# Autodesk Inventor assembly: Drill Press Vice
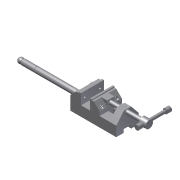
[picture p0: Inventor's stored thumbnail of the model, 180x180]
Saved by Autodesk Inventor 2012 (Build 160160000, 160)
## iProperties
Created: 2009-05
Part Number: Drill Press Vice
Document SubType Name: Assembly
Designer: Sham
Author: Sham
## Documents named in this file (9)
- C:\Users\CadCim\Documents\SAILESH\inventor-2011-fact-prt\c13-inv-2011-prt\c13_inv_2012_prt\fig-13-5 to 13-8\Drill Press Vice.iam
- C:\Users\CadCim\Documents\SAILESH\inventor-2011-fact-prt\c13-inv-2011-prt\c13_inv_2012_prt\fig-13-5 to 13-8\Base.ipt
- C:\Users\CadCim\Documents\SAILESH\inventor-2011-fact-prt\c13-inv-2011-prt\c13_inv_2012_prt\fig-13-5 to 13-8\Safety Handle.ipt
- C:\Users\CadCim\Documents\SAILESH\inventor-2011-fact-prt\c13-inv-2011-prt\c13_inv_2012_prt\fig-13-5 to 13-8\Jaw Face.ipt
- C:\Users\CadCim\Documents\SAILESH\inventor-2011-fact-prt\c13-inv-2011-prt\c13_inv_2012_prt\fig-13-5 to 13-8\Movable Jaw.ipt
- C:\Users\CadCim\Documents\SAILESH\inventor-2011-fact-prt\c13-inv-2011-prt\c13_inv_2012_prt\fig-13-5 to 13-8\Cap Screw.ipt
- C:\Users\CadCim\Documents\SAILESH\inventor-2011-fact-prt\c13-inv-2011-prt\c13_inv_2012_prt\fig-13-5 to 13-8\Clamp Screw Handle.ipt
- C:\Users\CadCim\Documents\SAILESH\inventor-2011-fact-prt\c13-inv-2011-prt\c13_inv_2012_prt\fig-13-5 to 13-8\Clamp Screw.ipt
- C:\Users\CadCim\Documents\SAILESH\inventor-2011-fact-prt\c13-inv-2011-prt\c13_inv_2012_prt\fig-13-5 to 13-8\Handle Stop.ipt
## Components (13 placed, 8 different names)
1. Base:1 — Mate:2, Mate:3, Mate:7, Insert:10, Insert:11, Insert:12, Insert:13
2. Safety Handle:1
3. Jaw Face:1 — Insert:8, Insert:9, Mate:7
4. Jaw Face:2 — Insert:10, Insert:11
5. Movable Jaw:1 — Mate:2, Mate:3, Insert:2, Insert:3, Insert:4, Insert:8, Insert:9
6. Cap Screw:1 — Insert:2
7. Cap Screw:2 — Insert:3
8. Cap Screw:3 — Insert:13
9. Cap Screw:4 — Insert:12
10. Clamp Screw:1 — Insert:4, Mate:6, Rotation/Translation:2
11. Clamp Screw Handle:1 — Mate:6, Insert:5, Insert:6, Rotation/Translation:2
12. Handle Stop:1 — Insert:6, Mate:8
13. Handle Stop:2 — Insert:5
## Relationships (17: Insert 11, Mate 5, RelateRotateTranslate 1)
- Mate:2: Base:1 ↔ Movable Jaw:1
- Mate:3: Base:1 ↔ Movable Jaw:1
- Insert:2: Movable Jaw:1 ↔ Cap Screw:1
- Insert:3: Movable Jaw:1 ↔ Cap Screw:2
- Insert:4: Movable Jaw:1 ↔ Clamp Screw:1
- Mate:6: Clamp Screw:1 ↔ Clamp Screw Handle:1
- Insert:5: Clamp Screw Handle:1 ↔ Handle Stop:2
- Insert:6: Clamp Screw Handle:1 ↔ Handle Stop:1
- Insert:8: Jaw Face:1 ↔ Movable Jaw:1
- Insert:9: Jaw Face:1 ↔ Movable Jaw:1
- Mate:7: Base:1 ↔ Jaw Face:1
- Rotation/Translation:2 [RelateRotateTranslate]: Clamp Screw:1 ↔ Clamp Screw Handle:1
- Mate:8: Handle Stop:1
- Insert:10: Base:1 ↔ Jaw Face:2
- Insert:11: Base:1 ↔ Jaw Face:2
- Insert:12: Base:1 ↔ Cap Screw:4
- Insert:13: Base:1 ↔ Cap Screw:3
